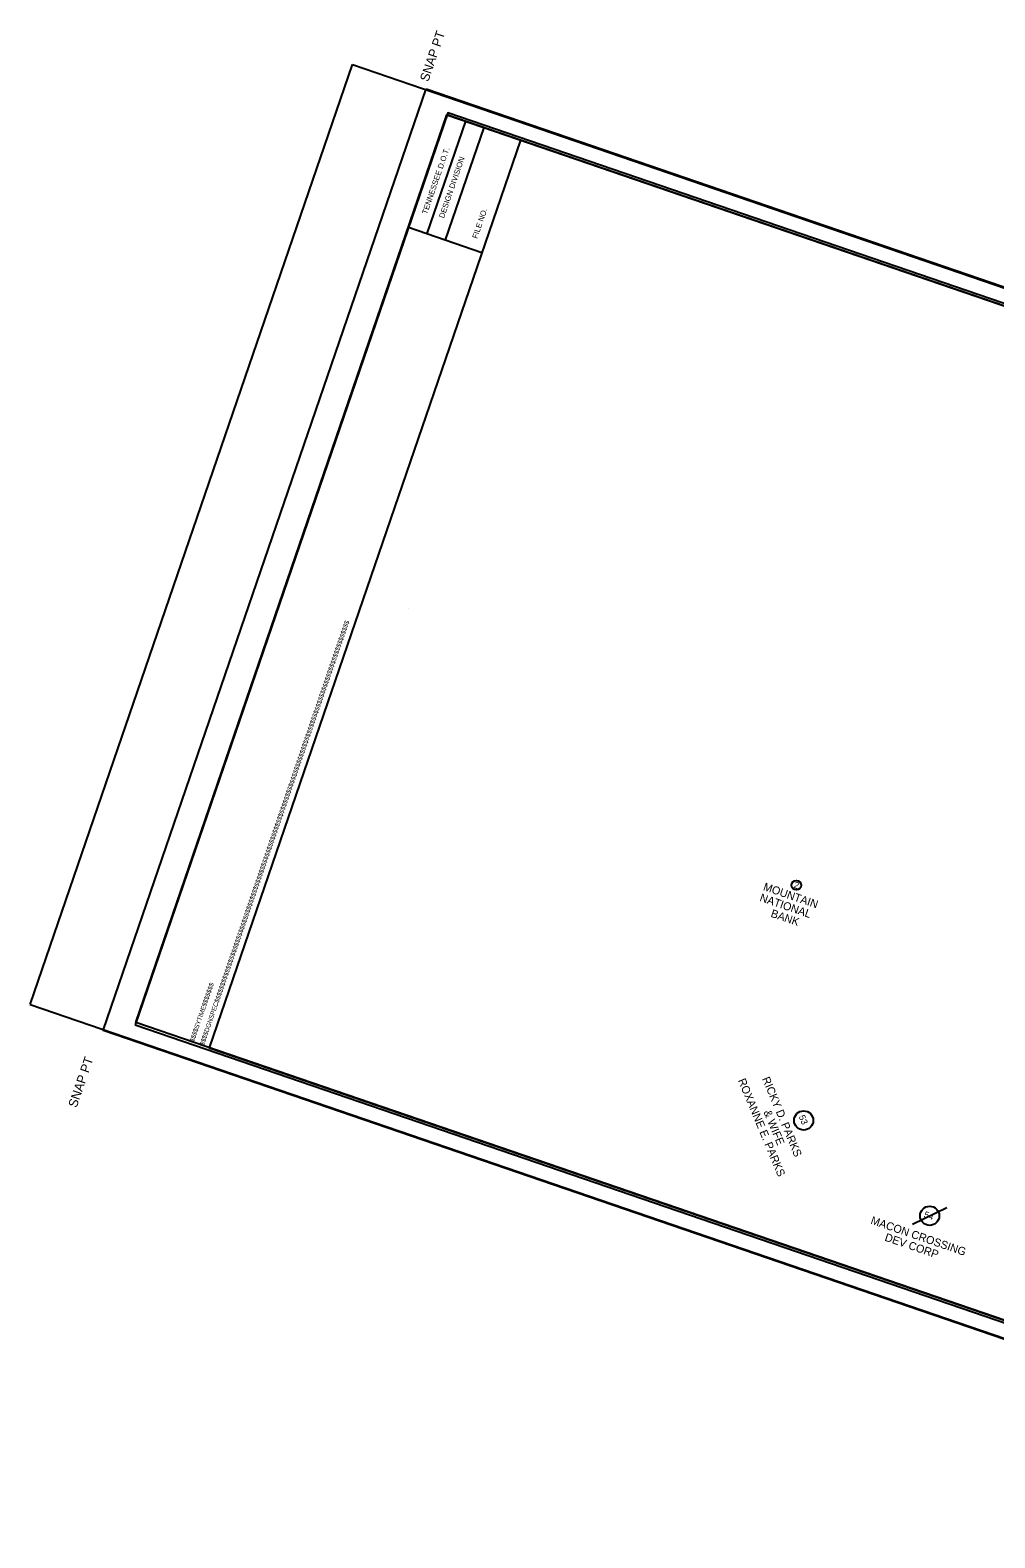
# Model space of a CAD drawing. Extents: x 2626331 to 2628652, y 569305 to 571035.
# Drawn here: x 2626331 to 2627386, y 569386 to 571035 of the extents above; entities that cross this region are included whole.
import ezdxf

# ---------------------------------------------------------------- set-up
doc = ezdxf.new("R2010")
doc.units = 0
for name, color, linetype in [('DESIGN - SCRATCH - User 1', 7, 'Continuous'), ('DESIGN - SHEET - Corner Text', 7, 'Continuous'), ('DESIGN - SHEET - Light Grid', 7, 'Continuous'), ('DESIGN - SHEET - Linework', 7, 'Continuous'), ('DESIGN - SHEET - Plot Shape', 7, 'Continuous'), ('SURVEY - PROPERTY - Owners', 7, 'Continuous'), ('SURVEY - PROPERTY - Tract Numbers', 7, 'Continuous')]:
    doc.layers.add(name, color=color, linetype=linetype)

msp = doc.modelspace()

# ---------------------------------------------------------------- linework, layer by layer
at = {"layer": 'DESIGN - SCRATCH - User 1'}
msp.add_line((2626744.1, 570402.3), (2626744.1, 570402.3), dxfattribs=at)
at = {"layer": 'DESIGN - SHEET - Light Grid'}
msp.add_lwpolyline([(2626445.3, 569947.1), (2628020.3, 569407.2), (2628362.4, 570405.2), (2626787.4, 570945.1)], close=True, dxfattribs=at)
at = {"layer": 'DESIGN - SHEET - Linework'}
for p, q in [((2626330.5, 569969.3), (2626683.1, 570997.9)), ((2626683.1, 570997.9), (2628385.9, 570414.3)), ((2626806.7, 570935.8), (2626764.5, 570812.9)), ((2626826.8, 570928.9), (2626784.7, 570806)), ((2626330.5, 569969.3), (2628033.2, 569385.6))]:
    msp.add_line(p, q, dxfattribs=at)
for points in [[(2626867, 570915.1), (2626786.5, 570942.7), (2626744.4, 570819.8), (2626824.9, 570792.3)], [(2626867, 570915.1), (2626526.5, 569921.9), (2628015.7, 569411.4), (2628356.1, 570404.7), (2626867, 570915.1)]]:
    msp.add_lwpolyline(points, dxfattribs=at)
at = {"layer": 'DESIGN - SHEET - Plot Shape'}
for points in [[(2626763.7, 570971.4), (2628371.8, 570420.1), (2628018.6, 569389.6), (2626410.4, 569940.8)], [(2626786.5, 570942.7), (2628356.1, 570404.7), (2628015.7, 569411.4), (2626446.1, 569949.5)]]:
    msp.add_lwpolyline(points, close=True, dxfattribs=at)
at = {"layer": 'SURVEY - PROPERTY - Tract Numbers'}
msp.add_line((2627295.9, 569728.7), (2627333.6, 569747.2), dxfattribs=at)
for centre, radius in [((2627168.9, 570099.8), 5.25), ((2627176.9, 569842.4), 10.5), ((2627314.8, 569738), 10.5)]:
    msp.add_circle(centre, radius, dxfattribs=at)

# ---------------------------------------------------------------- texts
at = {"layer": 'DESIGN - SHEET - Corner Text'}
for s, height, p in [('  SNAP PT', 10, (2626763.7, 570971.4)), ('TENNESSEE D.O.T.', 6, (2626764.8, 570833.5)), ('DESIGN DIVISION', 6, (2626783.3, 570829.2)), ('FILE NO.', 6, (2626819.7, 570806.8)), ('$$$$DGNSPEC$$$$$$$$$$$$$$$$$$$$$$$$$$$$$$$$$$$$$$$$$$$$$$$$$$$$$$$$$$$$$$$$$$$$$$$$$$$$$$$$$$$$$$$$$$$$$$$$$$$$$$$$$$$$$$$$$$$', 5.0001, (2626520.6, 569923.9)), ('$$$$SYTIME$$$$$$$', 5, (2626509.6, 569927.7)), ('SNAP PT  ', 10, (2626381.3, 569855.7))]:
    msp.add_text(s, height=height, rotation=71.0785, dxfattribs=at).set_placement(p)
at = {"layer": 'SURVEY - PROPERTY - Owners'}
for s, rotation, p in [('MOUNTAIN', 341.0785, (2627131.9, 570094.6)), ('NATIONAL', 341.0785, (2627128.1, 570082.7)), ('BANK', 341.0785, (2627140.2, 570065.4)), ('ROXANNE E. PARKS', 292.6154, (2627104.8, 569886.2)), ('RICKY D. PARKS', 292.6154, (2627131.2, 569888)), ('& WIFE', 292.6154, (2627132.8, 569851.6)), ('MACON CROSSING', 341.0785, (2627249.5, 569729.5)), ('DEV CORP ', 341.0785, (2627264.9, 569711))]:
    msp.add_text(s, height=8.75, rotation=rotation, dxfattribs=at).set_placement(p)
at = {"layer": 'SURVEY - PROPERTY - Tract Numbers'}
for s, rotation, p in [('2', 341.0785, (2627165.4, 570097.3)), ('53', 292.6154, (2627171.4, 569846.6)), ('54', 341.0785, (2627307.9, 569736.6))]:
    msp.add_text(s, height=7, rotation=rotation, dxfattribs=at).set_placement(p)

doc.saveas('drawing.dxf')
